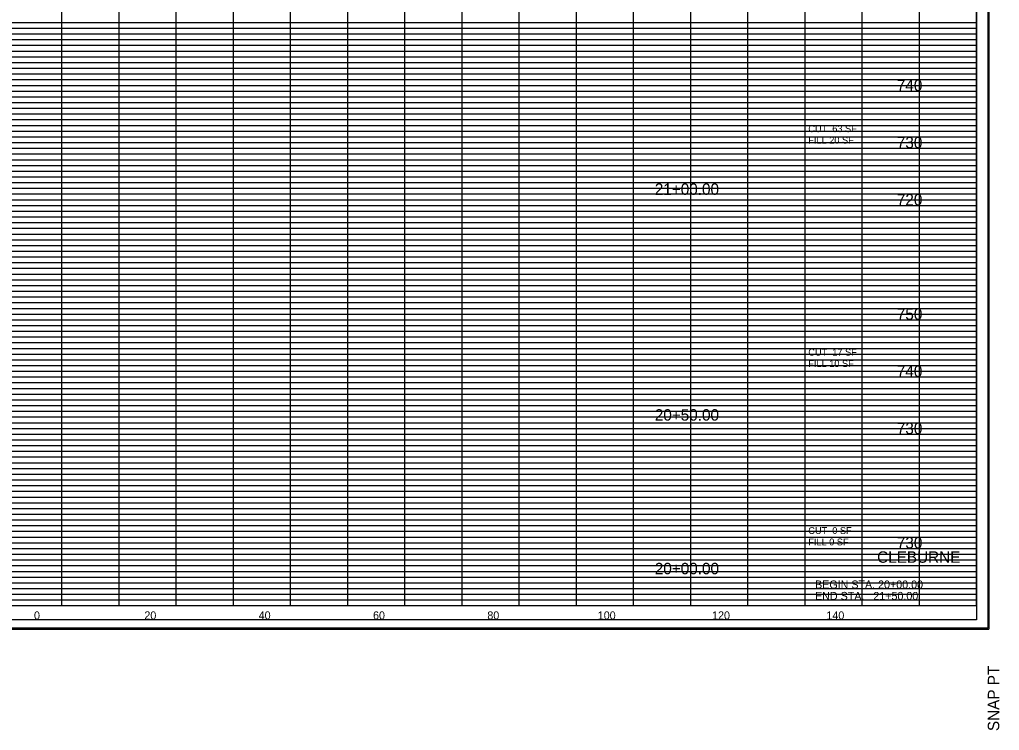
# Model space of a CAD drawing. Extents: x -200 to 1324, y -325 to 1497.
# Drawn here: x 1152.6 to 1324, y 978.2 to 1102.5 of the extents above; entities that cross this region are included whole.
import ezdxf

# ---------------------------------------------------------------- set-up
doc = ezdxf.new("R2010")
doc.units = 0
for name, color, linetype in [('DESIGN - SHEET - Corner Text', 7, 'Continuous'), ('DESIGN - SHEET - Light Grid', 7, 'Continuous'), ('DESIGN - SHEET - Linework', 7, 'Continuous'), ('DESIGN - SHEET - Plot Shape', 7, 'Continuous'), ('DESIGN - TYPICAL - Text', 7, 'Continuous')]:
    doc.layers.add(name, color=color, linetype=linetype)

msp = doc.modelspace()

# ---------------------------------------------------------------- linework, layer by layer
at = {"layer": 'DESIGN - SHEET - Light Grid'}
for p, q in [((1080, 1102), (1160, 1102)), ((1080, 1101), (1160, 1101)), ((1160, 1102), (1240, 1102)), ((1160, 1101), (1240, 1101)), ((1240, 1102), (1320, 1102)), ((1240, 1101), (1320, 1101)), ((1080, 1099), (1160, 1099)), ((1160, 1099), (1240, 1099)), ((1240, 1099), (1320, 1099)), ((1080, 1098), (1160, 1098)), ((1160, 1098), (1240, 1098)), ((1240, 1098), (1320, 1098)), ((1080, 1097), (1160, 1097)), ((1080, 1096), (1160, 1096)), ((1160, 1097), (1240, 1097)), ((1160, 1096), (1240, 1096)), ((1240, 1097), (1320, 1097)), ((1240, 1096), (1320, 1096)), ((1080, 1095), (1160, 1095)), ((1080, 1094), (1160, 1094)), ((1160, 1095), (1240, 1095)), ((1160, 1094), (1240, 1094)), ((1240, 1095), (1320, 1095)), ((1240, 1094), (1320, 1094)), ((1080, 1093), (1160, 1093)), ((1080, 1092), (1160, 1092)), ((1160, 1093), (1240, 1093)), ((1160, 1092), (1240, 1092)), ((1240, 1093), (1320, 1093)), ((1240, 1092), (1320, 1092)), ((1080, 1091), (1160, 1091)), ((1160, 1091), (1240, 1091)), ((1240, 1091), (1320, 1091)), ((1080, 1089), (1160, 1089)), ((1160, 1089), (1240, 1089)), ((1240, 1089), (1320, 1089)), ((1080, 1088), (1160, 1088)), ((1080, 1087), (1160, 1087)), ((1160, 1088), (1240, 1088)), ((1160, 1087), (1240, 1087)), ((1240, 1088), (1320, 1088)), ((1240, 1087), (1320, 1087)), ((1080, 1086), (1160, 1086)), ((1160, 1086), (1240, 1086)), ((1240, 1086), (1320, 1086)), ((1080, 1085), (1160, 1085)), ((1080, 1084), (1160, 1084)), ((1160, 1085), (1240, 1085)), ((1160, 1084), (1240, 1084)), ((1240, 1085), (1320, 1085)), ((1240, 1084), (1320, 1084)), ((1080, 1083), (1160, 1083)), ((1080, 1082), (1160, 1082)), ((1160, 1083), (1240, 1083)), ((1160, 1082), (1240, 1082)), ((1240, 1083), (1320, 1083)), ((1240, 1082), (1320, 1082)), ((1080, 1081), (1160, 1081)), ((1160, 1081), (1240, 1081)), ((1240, 1081), (1320, 1081)), ((1080, 1079), (1160, 1079)), ((1160, 1079), (1240, 1079)), ((1240, 1079), (1320, 1079)), ((1080, 1078), (1160, 1078)), ((1080, 1077), (1160, 1077)), ((1160, 1078), (1240, 1078)), ((1160, 1077), (1240, 1077)), ((1240, 1078), (1320, 1078)), ((1240, 1077), (1320, 1077)), ((1080, 1076), (1160, 1076)), ((1080, 1075), (1160, 1075)), ((1160, 1076), (1240, 1076)), ((1160, 1075), (1240, 1075)), ((1240, 1076), (1320, 1076)), ((1240, 1075), (1320, 1075)), ((1080, 1074), (1160, 1074)), ((1160, 1074), (1240, 1074)), ((1240, 1074), (1320, 1074)), ((1080, 1073), (1160, 1073)), ((1080, 1072), (1160, 1072)), ((1160, 1073), (1240, 1073)), ((1160, 1072), (1240, 1072)), ((1240, 1073), (1320, 1073)), ((1240, 1072), (1320, 1072)), ((1080, 1071), (1160, 1071)), ((1160, 1071), (1240, 1071)), ((1240, 1071), (1320, 1071)), ((1080, 1069), (1160, 1069)), ((1080, 1068), (1160, 1068)), ((1160, 1069), (1240, 1069)), ((1160, 1068), (1240, 1068)), ((1240, 1069), (1320, 1069)), ((1240, 1068), (1320, 1068)), ((1080, 1067), (1160, 1067)), ((1160, 1067), (1240, 1067)), ((1240, 1067), (1320, 1067)), ((1080, 1066), (1160, 1066)), ((1080, 1065), (1160, 1065)), ((1160, 1066), (1240, 1066)), ((1160, 1065), (1240, 1065)), ((1240, 1066), (1320, 1066)), ((1240, 1065), (1320, 1065)), ((1080, 1064), (1160, 1064)), ((1080, 1063), (1160, 1063)), ((1160, 1064), (1240, 1064)), ((1160, 1063), (1240, 1063)), ((1240, 1064), (1320, 1064)), ((1240, 1063), (1320, 1063)), ((1080, 1062), (1160, 1062)), ((1160, 1062), (1240, 1062)), ((1240, 1062), (1320, 1062)), ((1080, 1061), (1160, 1061)), ((1160, 1061), (1240, 1061)), ((1240, 1061), (1320, 1061)), ((1080, 1059), (1160, 1059)), ((1080, 1058), (1160, 1058)), ((1160, 1059), (1240, 1059)), ((1160, 1058), (1240, 1058)), ((1240, 1059), (1320, 1059)), ((1240, 1058), (1320, 1058)), ((1080, 1057), (1160, 1057)), ((1080, 1056), (1160, 1056)), ((1160, 1057), (1240, 1057)), ((1160, 1056), (1240, 1056)), ((1240, 1057), (1320, 1057)), ((1240, 1056), (1320, 1056)), ((1080, 1055), (1160, 1055)), ((1160, 1055), (1240, 1055)), ((1240, 1055), (1320, 1055)), ((1080, 1054), (1160, 1054)), ((1080, 1053), (1160, 1053)), ((1160, 1054), (1240, 1054)), ((1160, 1053), (1240, 1053)), ((1240, 1054), (1320, 1054)), ((1240, 1053), (1320, 1053)), ((1080, 1052), (1160, 1052)), ((1080, 1051), (1160, 1051)), ((1160, 1052), (1240, 1052)), ((1160, 1051), (1240, 1051)), ((1240, 1052), (1320, 1052)), ((1240, 1051), (1320, 1051)), ((1080, 1049), (1160, 1049)), ((1080, 1048), (1160, 1048)), ((1160, 1049), (1240, 1049)), ((1160, 1048), (1240, 1048)), ((1240, 1049), (1320, 1049)), ((1240, 1048), (1320, 1048)), ((1080, 1047), (1160, 1047)), ((1080, 1046), (1160, 1046)), ((1160, 1047), (1240, 1047)), ((1160, 1046), (1240, 1046)), ((1240, 1047), (1320, 1047)), ((1240, 1046), (1320, 1046)), ((1080, 1045), (1160, 1045)), ((1080, 1044), (1160, 1044)), ((1160, 1045), (1240, 1045)), ((1160, 1044), (1240, 1044)), ((1240, 1045), (1320, 1045)), ((1240, 1044), (1320, 1044)), ((1080, 1043), (1160, 1043)), ((1160, 1043), (1240, 1043)), ((1240, 1043), (1320, 1043)), ((1080, 1042), (1160, 1042)), ((1080, 1041), (1160, 1041)), ((1160, 1042), (1240, 1042)), ((1160, 1041), (1240, 1041)), ((1240, 1042), (1320, 1042)), ((1240, 1041), (1320, 1041)), ((1080, 1039), (1160, 1039)), ((1160, 1039), (1240, 1039)), ((1240, 1039), (1320, 1039)), ((1080, 1038), (1160, 1038)), ((1160, 1038), (1240, 1038)), ((1240, 1038), (1320, 1038)), ((1080, 1037), (1160, 1037)), ((1080, 1036), (1160, 1036)), ((1160, 1037), (1240, 1037)), ((1160, 1036), (1240, 1036)), ((1240, 1037), (1320, 1037)), ((1240, 1036), (1320, 1036)), ((1080, 1035), (1160, 1035)), ((1080, 1034), (1160, 1034)), ((1160, 1035), (1240, 1035)), ((1160, 1034), (1240, 1034)), ((1240, 1035), (1320, 1035)), ((1240, 1034), (1320, 1034)), ((1080, 1033), (1160, 1033)), ((1080, 1032), (1160, 1032)), ((1160, 1033), (1240, 1033)), ((1160, 1032), (1240, 1032)), ((1240, 1033), (1320, 1033)), ((1240, 1032), (1320, 1032)), ((1080, 1031), (1160, 1031)), ((1160, 1031), (1240, 1031)), ((1240, 1031), (1320, 1031)), ((1080, 1029), (1160, 1029)), ((1160, 1029), (1240, 1029)), ((1240, 1029), (1320, 1029)), ((1080, 1028), (1160, 1028)), ((1080, 1027), (1160, 1027)), ((1160, 1028), (1240, 1028)), ((1160, 1027), (1240, 1027)), ((1240, 1028), (1320, 1028)), ((1240, 1027), (1320, 1027)), ((1080, 1026), (1160, 1026)), ((1160, 1026), (1240, 1026)), ((1240, 1026), (1320, 1026)), ((1080, 1025), (1160, 1025)), ((1080, 1024), (1160, 1024)), ((1160, 1025), (1240, 1025)), ((1160, 1024), (1240, 1024)), ((1240, 1025), (1320, 1025)), ((1240, 1024), (1320, 1024)), ((1080, 1023), (1160, 1023)), ((1080, 1022), (1160, 1022)), ((1160, 1023), (1240, 1023)), ((1160, 1022), (1240, 1022)), ((1240, 1023), (1320, 1023)), ((1240, 1022), (1320, 1022)), ((1080, 1021), (1160, 1021)), ((1160, 1021), (1240, 1021)), ((1240, 1021), (1320, 1021)), ((1080, 1019), (1160, 1019)), ((1160, 1019), (1240, 1019)), ((1240, 1019), (1320, 1019)), ((1080, 1018), (1160, 1018)), ((1080, 1017), (1160, 1017)), ((1160, 1018), (1240, 1018)), ((1160, 1017), (1240, 1017)), ((1240, 1018), (1320, 1018)), ((1240, 1017), (1320, 1017)), ((1080, 1016), (1160, 1016)), ((1080, 1015), (1160, 1015)), ((1160, 1016), (1240, 1016)), ((1160, 1015), (1240, 1015)), ((1240, 1016), (1320, 1016)), ((1240, 1015), (1320, 1015)), ((1080, 1014), (1160, 1014)), ((1160, 1014), (1240, 1014)), ((1240, 1014), (1320, 1014)), ((1080, 1013), (1160, 1013)), ((1080, 1012), (1160, 1012)), ((1160, 1013), (1240, 1013)), ((1160, 1012), (1240, 1012)), ((1240, 1013), (1320, 1013)), ((1240, 1012), (1320, 1012)), ((1080, 1011), (1160, 1011)), ((1160, 1011), (1240, 1011)), ((1240, 1011), (1320, 1011)), ((1080, 1009), (1160, 1009)), ((1080, 1008), (1160, 1008)), ((1160, 1009), (1240, 1009)), ((1160, 1008), (1240, 1008)), ((1240, 1009), (1320, 1009)), ((1240, 1008), (1320, 1008)), ((1080, 1007), (1160, 1007)), ((1160, 1007), (1240, 1007)), ((1240, 1007), (1320, 1007)), ((1080, 1006), (1160, 1006)), ((1080, 1005), (1160, 1005)), ((1160, 1006), (1240, 1006)), ((1160, 1005), (1240, 1005)), ((1240, 1006), (1320, 1006)), ((1240, 1005), (1320, 1005)), ((1080, 1004), (1160, 1004)), ((1080, 1003), (1160, 1003)), ((1160, 1004), (1240, 1004)), ((1160, 1003), (1240, 1003)), ((1240, 1004), (1320, 1004)), ((1240, 1003), (1320, 1003)), ((1080, 1002), (1160, 1002)), ((1160, 1002), (1240, 1002)), ((1240, 1002), (1320, 1002)), ((1080, 1001), (1160, 1001)), ((1160, 1001), (1240, 1001)), ((1240, 1001), (1320, 1001))]:
    msp.add_line(p, q, dxfattribs=at)
at = {"layer": 'DESIGN - SHEET - Linework'}
for p, q in [((1322.17, 1214.14), (1322.17, 995.86)), ((1160, 1000), (1160, 1210)), ((1170, 1000), (1170, 1210)), ((1180, 1000), (1180, 1210)), ((1190, 1000), (1190, 1210)), ((1200, 1000), (1200, 1210)), ((1210, 1000), (1210, 1210)), ((1220, 1000), (1220, 1210)), ((1230, 1000), (1230, 1210)), ((1240, 1000), (1240, 1210)), ((1250, 1000), (1250, 1210)), ((1260, 1000), (1260, 1210)), ((1270, 1000), (1270, 1210)), ((1280, 1000), (1280, 1200)), ((1290, 1000), (1290, 1200)), ((1300, 1000), (1300, 1200)), ((1310, 1000), (1310, 1200)), ((1000, 1100), (1320, 1100)), ((1000, 1090), (1320, 1090)), ((1000, 1080), (1320, 1080)), ((1000, 1070), (1320, 1070)), ((1000, 1060), (1320, 1060)), ((1000, 1050), (1320, 1050)), ((1000, 1040), (1320, 1040)), ((1000, 1030), (1320, 1030)), ((1000, 1020), (1320, 1020)), ((1000, 1010), (1320, 1010)), ((981.77, 995.86), (1322.17, 995.86))]:
    msp.add_line(p, q, dxfattribs=at)
msp.add_lwpolyline([(1000, 1210), (1000, 1000), (1320, 1000), (1320, 1210), (1000, 1210)], dxfattribs=at)
at = {"layer": 'DESIGN - SHEET - Plot Shape'}
for points in [[(981.97, 1213.94), (1321.97, 1213.94), (1321.97, 996.06), (981.97, 996.06)], [(991.5, 1210), (1320, 1210), (1320, 997.5), (991.5, 997.5)]]:
    msp.add_lwpolyline(points, close=True, dxfattribs=at)

# ---------------------------------------------------------------- texts
at = {"layer": 'DESIGN - SHEET - Corner Text'}
for s, height, p in [('CLEBURNE', 2, (1302.61, 1007.5)), ('BEGIN STA. 20+00.00', 1.4, (1291.75, 1003)), ('END STA.   21+50.00', 1.4, (1291.75, 1001))]:
    msp.add_text(s, height=height, dxfattribs=at).set_placement(p)
msp.add_text('SNAP PT  ', height=2, rotation=90, dxfattribs=at).set_placement((1323.97, 978.06))
at = {"layer": 'DESIGN - TYPICAL - Text'}
for s, height, p in [('     740     ', 2, (1302.34, 1090)), ('CUT  63 SF', 1.2, (1290.57, 1082.82)), ('FILL 20 SF', 1.2, (1290.57, 1080.82)), ('     730     ', 2, (1302.34, 1080)), ('     21+00.00     ', 2, (1260, 1071.85)), ('     720     ', 2, (1302.34, 1070)), ('     750     ', 2, (1302.34, 1050)), ('CUT  17 SF', 1.2, (1290.57, 1043.73)), ('FILL 10 SF', 1.2, (1290.57, 1041.73)), ('     740     ', 2, (1302.34, 1040)), ('     20+50.00     ', 2, (1260, 1032.36)), ('     730     ', 2, (1302.34, 1030)), ('CUT  0 SF', 1.2, (1290.57, 1012.54)), ('FILL 0 SF', 1.2, (1290.57, 1010.54)), ('     730     ', 2, (1302.34, 1010)), ('     20+00.00     ', 2, (1260, 1005.49)), ('     0     ', 1.4, (1152.51, 997.6)), ('     0     ', 1.4, (1152.51, 997.6)), ('     20     ', 1.4, (1171.82, 997.6)), ('     40     ', 1.4, (1191.82, 997.6)), ('     60     ', 1.4, (1211.82, 997.6)), ('     80     ', 1.4, (1231.82, 997.6)), ('     100     ', 1.4, (1251.14, 997.6)), ('     120     ', 1.4, (1271.14, 997.6)), ('     140     ', 1.4, (1291.14, 997.6))]:
    msp.add_text(s, height=height, dxfattribs=at).set_placement(p)

doc.saveas('drawing.dxf')
